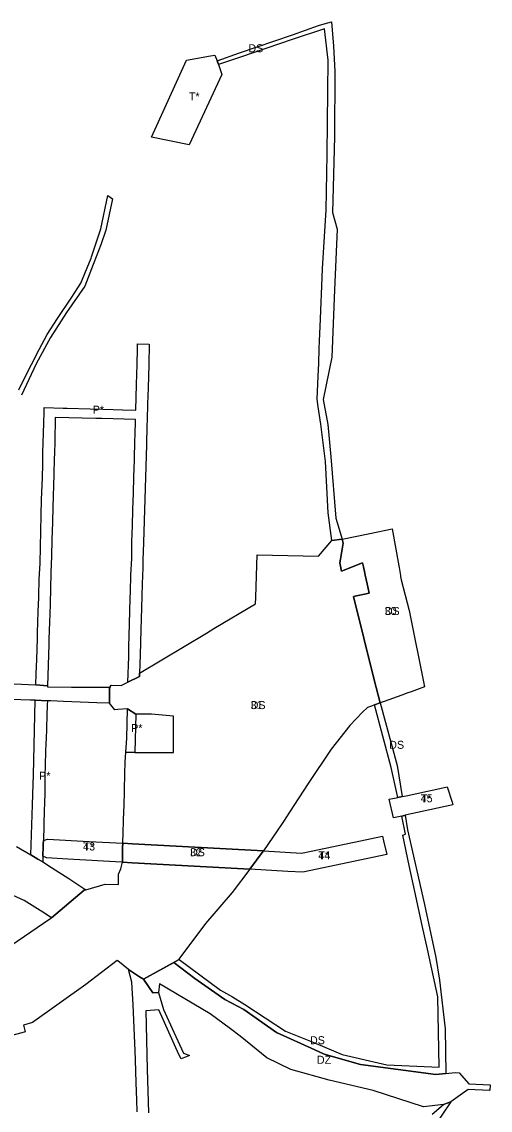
# Model space of a CAD drawing. Extents: x -501732 to -497665, y -1142022 to -1138283.
# Drawn here: x -498074 to -497665, y -1140690 to -1139739 of the extents above; entities that cross this region are included whole.
import ezdxf

# ---------------------------------------------------------------- set-up
doc = ezdxf.new("R2010")
doc.units = 0
for name, color, linetype in [('22', 7, 'Continuous'), ('23', 7, 'Continuous'), ('4', 7, 'Continuous'), ('43', 7, 'Continuous'), ('5', 7, 'Continuous'), ('61', 7, 'Continuous'), ('7', 7, 'Continuous')]:
    doc.layers.add(name, color=color, linetype=linetype)

msp = doc.modelspace()

# ---------------------------------------------------------------- linework, layer by layer
at = {"layer": '22'}
msp.add_lwpolyline([(-497903.5, -1139772.63), (-497902.29, -1139775.97), (-497899.3, -1139784.73), (-497928.01, -1139846.19), (-497960.97, -1139839.57), (-497930.31, -1139772.01), (-497909.09, -1139768.28), (-497905.42, -1139767.64)], close=True, dxfattribs=at)
at = {"layer": '23'}
for points in [[(-497742.025, -1140433.137), (-497749.305, -1140434.783), (-497752.954, -1140418.426), (-497745.487, -1140417.036), (-497741.556, -1140416.179), (-497738.052, -1140415.414), (-497719.331, -1140411.328), (-497714.01, -1140410.166), (-497702.315, -1140407.614), (-497697.93, -1140421.1), (-497697.403, -1140423.438), (-497710.808, -1140426.361), (-497738.975, -1140432.504), (-497739.599, -1140432.64)], [(-497985.937, -1140456.951), (-497986.07, -1140460.79), (-497986.174, -1140473.486), (-497987.181, -1140473.429), (-498033.913, -1140470.801), (-498052.607, -1140469.75), (-498055.788, -1140468.341), (-498055.53, -1140459.47), (-498055.484, -1140457.899), (-498055.384, -1140454.516), (-498051.68, -1140453.276), (-498015.461, -1140455.312)], [(-497757.956, -1140454.716), (-497755.151, -1140466.802), (-497828.392, -1140482.359), (-497841.639, -1140481.614), (-497874.808, -1140479.748), (-497863.221, -1140463.874), (-497862.96, -1140463.494), (-497829.666, -1140465.761), (-497821.285, -1140463.981), (-497777.943, -1140454.775), (-497758.85, -1140450.865)]]:
    msp.add_lwpolyline(points, close=True, dxfattribs=at)
at = {"layer": '4'}
for points in [[(-497809.95, -1139740.28), (-497803.397, -1139738.564), (-497801.75, -1139759.81), (-497800.42, -1139782.06), (-497800.8, -1139839.1), (-497802.42, -1139905.22), (-497798.43, -1139920.05), (-497800.8, -1139973.1), (-497803.18, -1140031.89), (-497810.64, -1140069), (-497806.7, -1140090.71), (-497803.97, -1140118.97), (-497799.48, -1140172.76), (-497794.171, -1140191.113), (-497803.04, -1140192.08), (-497806.37, -1140168.09), (-497808.7, -1140122.98), (-497812.78, -1140090.35), (-497814.95, -1140075.17), (-497815.9, -1140068.55), (-497815.62, -1140061.94), (-497815.05, -1140048.49), (-497814.59, -1140037.3), (-497814.06, -1140024.31), (-497813.79, -1140017.83), (-497812.98, -1139998.22), (-497811.57, -1139962.24), (-497811.26, -1139954.45), (-497808.19, -1139903.25), (-497807.14, -1139854.48), (-497806.44, -1139772.23), (-497809.68, -1139744.7), (-497837.75, -1139753.95), (-497882.9, -1139769.54), (-497902.29, -1139775.97), (-497903.5, -1139772.63), (-497883.9, -1139765.85), (-497837.54, -1139749.94), (-497814.7, -1139741.95)], [(-497741.556, -1140416.179), (-497745.487, -1140417.036), (-497751.17, -1140390.61), (-497765.849, -1140336.021), (-497760.746, -1140334.19), (-497745.87, -1140388.9)], [(-497704.11, -1140619.29), (-497703.28, -1140658.33), (-497709.26, -1140658.99), (-497712.1, -1140659.31), (-497778.08, -1140650.46), (-497809.84, -1140641.44), (-497817.9, -1140637.68), (-497851.6, -1140622.37), (-497879.94, -1140602.25), (-497896.631, -1140593.598), (-497922.968, -1140575.185), (-497941.355, -1140561.109), (-497937.22, -1140558.81), (-497936.62, -1140558.714), (-497900.36, -1140585.38), (-497889.91, -1140591.32), (-497879.264, -1140597.891), (-497843.724, -1140621.333), (-497818.9, -1140631.1), (-497794.134, -1140641.735), (-497754.968, -1140650.675), (-497709.37, -1140652.85), (-497710.44, -1140591.41), (-497719.52, -1140549.583), (-497724.02, -1140528.855), (-497730.468, -1140499.157), (-497735.428, -1140476.31), (-497741.17, -1140449.86), (-497738.59, -1140449.11), (-497742.025, -1140433.137), (-497739.599, -1140432.64), (-497738.975, -1140432.504), (-497736.978, -1140445.132), (-497722.062, -1140510.625), (-497712.04, -1140556.773), (-497708.97, -1140576.79)]]:
    msp.add_lwpolyline(points, close=True, dxfattribs=at)
msp.add_lwpolyline([(-498080.83, -1140317.66), (-498061.89, -1140318.32), (-498051.72, -1140319.34), (-498051.75, -1140320.31), (-498030.79, -1140320.34), (-498011.52, -1140320.57), (-498002.25, -1140320.5), (-497997.053, -1140320.376), (-497997.617, -1140321.437), (-497997.649, -1140330.097), (-497997.64, -1140334.52), (-498008.74, -1140334.09), (-498037.792, -1140332.9), (-498049.02, -1140332.44), (-498051.92, -1140332.32), (-498062.53, -1140331.84), (-498067.02, -1140331.73), (-498116.41, -1140330.16)], dxfattribs=at)
at = {"layer": '43'}
for points in [[(-498076.93, -1140060.36), (-498067.12, -1140040.83), (-498065.77, -1140038.15), (-498058.96, -1140025.11), (-498052.15, -1140012.08), (-498043.03, -1139998.07), (-498030.37, -1139979.5), (-498022.56, -1139967.15), (-498013.7, -1139945.33), (-498013.29, -1139944.08), (-498005.22, -1139919.56), (-497999.11, -1139890.59), (-497994.884, -1139893.368), (-498000.78, -1139920.93), (-498005.08, -1139933.72), (-498011.32, -1139949.27), (-498011.9, -1139950.71), (-498019.07, -1139969.8), (-498035.04, -1139992.75), (-498049.31, -1140014.76), (-498061.7, -1140037.59), (-498074.46, -1140064.99)], [(-497973.452, -1140691.911), (-497973.8, -1140681.43), (-497974.31, -1140666.39), (-497974.74, -1140646.39), (-497975.01, -1140638.43), (-497976, -1140618.24), (-497976.81, -1140598.31), (-497978.03, -1140578.33), (-497981.02, -1140567.46), (-497971.23, -1140573.7), (-497967.87, -1140575.85), (-497959.56, -1140587.67), (-497954.83, -1140587.61), (-497950.37, -1140602.37), (-497941.23, -1140622.22), (-497932.86, -1140640.39), (-497927.56, -1140642.59), (-497934.91, -1140645.49), (-497936.82, -1140641.63), (-497954.43, -1140602.68), (-497965.83, -1140603.55), (-497964.62, -1140654.4), (-497963.48, -1140692.74)], [(-497715.23, -1140693.81), (-497705.51, -1140685.39), (-497699.12, -1140683.04), (-497714.85, -1140706.52)]]:
    msp.add_lwpolyline(points, dxfattribs=at)
for points in [[(-498054.82, -1140079.71), (-498054.83, -1140075.94), (-498038.09, -1140076.42), (-498034.57, -1140076.51), (-498014.44, -1140077.12), (-498003.484, -1140077.454), (-497994.45, -1140077.73), (-497986.15, -1140077.99), (-497974.47, -1140078.35), (-497973.88, -1140055.76), (-497973.42, -1140038.36), (-497973.05, -1140024.47), (-497972.94, -1140020.12), (-497962.79, -1140020.41), (-497963.26, -1140038.61), (-497963.85, -1140058.8), (-497964.3, -1140072.76), (-497964.76, -1140086.73), (-497964.86, -1140091.83), (-497965.21, -1140108.5), (-497967.82, -1140193.95), (-497968.07, -1140202.14), (-497968.28, -1140208.91), (-497968.46, -1140216.13), (-497968.7, -1140223.18), (-497968.93, -1140230.1), (-497969.61, -1140251.02), (-497970.24, -1140270.27), (-497970.89, -1140292.24), (-497971.26, -1140308.34), (-497971.33, -1140311.03), (-497981.4, -1140315.98), (-497980.77, -1140293.79), (-497980.759, -1140293.251), (-497980.6, -1140285.1), (-497980.18, -1140265.21), (-497979.39, -1140242.57), (-497979.22, -1140237.02), (-497978.79, -1140222.57), (-497978.18, -1140208.03), (-497978.15, -1140207.04), (-497977.93, -1140193.45), (-497977.51, -1140179.27), (-497977.09, -1140164.98), (-497976.66, -1140150.68), (-497976.24, -1140136.39), (-497975.82, -1140122.09), (-497975.29, -1140104.17), (-497975.18, -1140100.61), (-497974.76, -1140086.42), (-498004.329, -1140085.623), (-498009.63, -1140085.48), (-498044.98, -1140084.53), (-498045.43, -1140105.7), (-498045.8, -1140116.2), (-498045.95, -1140120.5), (-498046.31, -1140134.48), (-498047.11, -1140162.92), (-498047.48, -1140176.22), (-498047.91, -1140191.6), (-498048.33, -1140205.79), (-498048.75, -1140220.07), (-498049.18, -1140234.51), (-498049.559, -1140247.159), (-498049.6, -1140248.54), (-498050.04, -1140263.52), (-498050.48, -1140278.43), (-498050.622, -1140283.231), (-498050.89, -1140292.25), (-498051.72, -1140319.34), (-498061.89, -1140318.32), (-498061.58, -1140308.6), (-498061.2, -1140296.41), (-498060.62, -1140277.91), (-498060.46, -1140272.92), (-498059.88, -1140254.43), (-498059.492, -1140241.92), (-498059.44, -1140240.26), (-498059, -1140226.24), (-498058.33, -1140212.15), (-498057.99, -1140198.15), (-498057.65, -1140184.15), (-498057.31, -1140170.16), (-498056.94, -1140156.38), (-498056.72, -1140150.13), (-498056.26, -1140137.11), (-498055.98, -1140125.71), (-498055.73, -1140115.3), (-498055.07, -1140089.45)], [(-498051.92, -1140332.32), (-498052.04, -1140335.9), (-498052.38, -1140345.52), (-498053.09, -1140366.51), (-498053.17, -1140368.51), (-498053.72, -1140387.1), (-498053.98, -1140399.6), (-498054.229, -1140411.567), (-498054.47, -1140423.19), (-498054.58, -1140427.18), (-498055, -1140441.48), (-498055.384, -1140454.516), (-498055.484, -1140457.899), (-498055.53, -1140459.47), (-498055.788, -1140468.341), (-498055.93, -1140473.24), (-498060.19, -1140470.74), (-498066.42, -1140467), (-498065.01, -1140423.28), (-498064.36, -1140405.43), (-498064.16, -1140397.43), (-498062.53, -1140331.84)], [(-497975.381, -1140377.464), (-497983.185, -1140377.342), (-497982.32, -1140365.37), (-497981.91, -1140339.55), (-497974.54, -1140344.08)]]:
    msp.add_lwpolyline(points, close=True, dxfattribs=at)
at = {"layer": '5'}
for points in [[(-497750.361, -1140182.123), (-497744.65, -1140214.23), (-497744.34, -1140215.94), (-497743.12, -1140222.81), (-497742.97, -1140223.61), (-497742.46, -1140226.49), (-497735.58, -1140253.46), (-497722.038, -1140320.293), (-497733.802, -1140324.516), (-497736.638, -1140325.534), (-497741.761, -1140327.373), (-497757.255, -1140332.936), (-497760.746, -1140334.19), (-497766.22, -1140314.06), (-497784.27, -1140241.09), (-497770.35, -1140238.29), (-497771.3, -1140234.04), (-497772.19, -1140230.04), (-497773.87, -1140222.54), (-497774.27, -1140220.73), (-497775.52, -1140215.16), (-497776.29, -1140211.71), (-497794.66, -1140218.96), (-497796.02, -1140211.8), (-497795.48, -1140208.51), (-497793.18, -1140194.54), (-497794.171, -1140191.113), (-497769.85, -1140186.122)], [(-497793.18, -1140194.54), (-497795.48, -1140208.51), (-497796.02, -1140211.8), (-497794.66, -1140218.96), (-497776.29, -1140211.71), (-497775.52, -1140215.16), (-497774.27, -1140220.73), (-497773.87, -1140222.54), (-497772.19, -1140230.04), (-497771.3, -1140234.04), (-497770.35, -1140238.29), (-497784.27, -1140241.09), (-497766.22, -1140314.06), (-497760.746, -1140334.19), (-497765.849, -1140336.021), (-497768.534, -1140336.985), (-497771.924, -1140338.202), (-497776.305, -1140342.26), (-497787.404, -1140354.097), (-497803.679, -1140374.661), (-497823.893, -1140404.582), (-497840.21, -1140429.769), (-497845.516, -1140437.96), (-497846.62, -1140439.663), (-497862.96, -1140463.494), (-497977.396, -1140457.425), (-497985.937, -1140456.951), (-497984.944, -1140428.367), (-497984.83, -1140425.08), (-497984.067, -1140395.824), (-497983.81, -1140385.99), (-497983.185, -1140377.342), (-497975.381, -1140377.464), (-497957.21, -1140377.58), (-497941.564, -1140377.56), (-497941.57, -1140368.44), (-497941.52, -1140345.9), (-497960.94, -1140344.13), (-497972.87, -1140344.1), (-497974.54, -1140344.08), (-497981.91, -1140339.55), (-497990.299, -1140340.023), (-497992.965, -1140340.174), (-497997.64, -1140334.52), (-497997.649, -1140330.097), (-497997.617, -1140321.437), (-497997.053, -1140320.376), (-497996.942, -1140320.168), (-497996.24, -1140318.85), (-497987.3, -1140318.88), (-497981.4, -1140315.98), (-497971.33, -1140311.03), (-497971.26, -1140308.34), (-497912.788, -1140273.253), (-497906.46, -1140269.12), (-497869.75, -1140247.65), (-497869.596, -1140242.152), (-497869.32, -1140232.34), (-497868.54, -1140204.71), (-497814.724, -1140205.764), (-497803.04, -1140192.08), (-497794.171, -1140191.113)], [(-497863.221, -1140463.874), (-497874.808, -1140479.748), (-497977.812, -1140473.956), (-497986.174, -1140473.486), (-497986.07, -1140460.79), (-497985.937, -1140456.951), (-497977.396, -1140457.425), (-497862.96, -1140463.494)]]:
    msp.add_lwpolyline(points, close=True, dxfattribs=at)
msp.add_lwpolyline([(-498100.702, -1140557.857), (-498049.646, -1140523.081), (-498048.385, -1140522.079), (-498019.752, -1140498.076), (-498018.382, -1140497.674), (-498001.33, -1140492.67), (-497989.83, -1140492.96), (-497989.6, -1140483.98), (-497987.8, -1140479.4), (-497986.174, -1140473.486), (-497977.812, -1140473.956), (-497874.808, -1140479.748), (-497890.3, -1140499.996), (-497913.717, -1140527.13), (-497936.936, -1140558.427), (-497936.83, -1140558.56), (-497936.62, -1140558.714), (-497937.22, -1140558.81), (-497967.87, -1140575.85), (-497971.23, -1140573.7), (-497981.02, -1140567.46), (-497990.31, -1140559.8), (-497990.749, -1140559.512), (-498018.24, -1140580.59), (-498064.77, -1140613.68), (-498072.91, -1140615.93), (-498071.35, -1140621.9), (-498074.25, -1140622.66), (-498092.81, -1140627.56)], dxfattribs=at)
at = {"layer": '7'}
msp.add_lwpolyline([(-498078.87, -1140459.94), (-498066.42, -1140467), (-498060.19, -1140470.74), (-498055.93, -1140473.24), (-498048.36, -1140478.05), (-498033.01, -1140487.89), (-498018.382, -1140497.674), (-498019.752, -1140498.076), (-498048.385, -1140522.079), (-498055.98, -1140517.15), (-498072.23, -1140507.08), (-498084.94, -1140501.15)], dxfattribs=at)
msp.add_lwpolyline([(-497879.94, -1140602.25), (-497851.6, -1140622.37), (-497817.9, -1140637.68), (-497809.84, -1140641.44), (-497778.08, -1140650.46), (-497712.1, -1140659.31), (-497709.26, -1140658.99), (-497703.28, -1140658.33), (-497695.17, -1140657.43), (-497691.84, -1140657.78), (-497683.37, -1140667.28), (-497664.59, -1140668.32), (-497664.63, -1140668.75), (-497665.07, -1140672.88), (-497665.12, -1140673.27), (-497683.84, -1140672.19), (-497690.827, -1140677.152), (-497699.12, -1140683.04), (-497705.51, -1140685.39), (-497723.05, -1140687.37), (-497766.84, -1140673.11), (-497805.55, -1140664.16), (-497839.03, -1140654.82), (-497860.05, -1140644.73), (-497883.28, -1140625.68), (-497891.85, -1140619.36), (-497909.67, -1140606.22), (-497953.88, -1140579.91), (-497954.83, -1140587.61), (-497959.56, -1140587.67), (-497967.87, -1140575.85), (-497941.355, -1140561.109), (-497922.968, -1140575.185), (-497896.631, -1140593.598)], close=True, dxfattribs=at)

# ---------------------------------------------------------------- texts
at = {"layer": '22'}
msp.add_text('T*', height=7, rotation=359.415368, dxfattribs=at).set_placement((-497928.164, -1139807.275))
at = {"layer": '23'}
for rotation, p in [(359.415368, (-497725.389, -1140421.135)), (359.41537, (-498020.636, -1140463.285)), (359.41537, (-497814.92, -1140471.07))]:
    msp.add_text('T*', height=7, rotation=rotation, dxfattribs=at).set_placement(p)
at = {"layer": '4'}
for p in [(-497876.084, -1139765.2), (-497752.911, -1140374.36), (-497822.234, -1140632.708)]:
    msp.add_text('DS', height=7, dxfattribs=at).set_placement(p)
at = {"layer": '43'}
for rotation, p in [(359.497417, (-498012.272, -1140081.291)), (359.497419, (-497978.649, -1140359.662))]:
    msp.add_text('P*', height=7, rotation=rotation, dxfattribs=at).set_placement(p)
msp.add_text('P*', height=7, dxfattribs=at).set_placement((-498059.078, -1140401.422))
at = {"layer": '5'}
for p in [(-497756.852, -1140257.362), (-497874.117, -1140339.638), (-497927.135, -1140468.296)]:
    msp.add_text('DS', height=7, dxfattribs=at).set_placement(p)
at = {"layer": '61'}
for s, p in [('30', (-497756.869, -1140257.362)), ('31', (-497874.133, -1140339.638)), ('45', (-497725.381, -1140421.134)), ('43', (-498020.628, -1140463.284)), ('32', (-497927.152, -1140468.296)), ('44', (-497814.912, -1140471.07))]:
    msp.add_text(s, height=7, dxfattribs=at).set_placement(p)
at = {"layer": '7'}
msp.add_text('DZ', height=7, dxfattribs=at).set_placement((-497816.154, -1140649.814))

doc.saveas('drawing.dxf')
